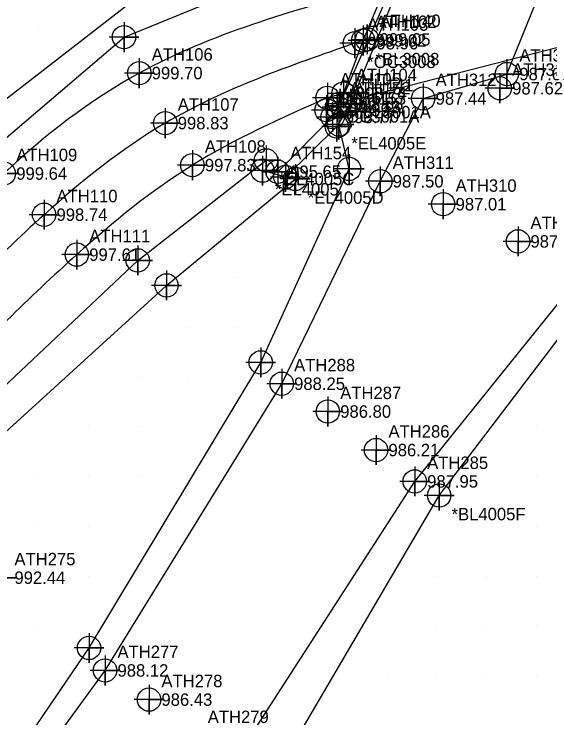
# Model space of a CAD drawing. Extents: x 1116680 to 1117499, y 661040 to 661703.
# Drawn here: x 1116955 to 1117062.7, y 661221.5 to 661363 of the extents above; entities that cross this region are included whole.
import ezdxf

# ---------------------------------------------------------------- set-up
doc = ezdxf.new("R2010")
doc.units = 0
for name, color, linetype in [('Exist DTM Breakline', 7, 'Continuous'), ('Exist DTM Breakline Cogo Comment', 7, 'Continuous'), ('Exist DTM Breakline Cogo Point CELL', 7, 'Continuous'), ('Exist DTM Crownline', 7, 'Continuous'), ('Exist DTM Crownline Cogo Comment', 7, 'Continuous'), ('Exist DTM Crownline Cogo Elevation', 7, 'Continuous'), ('Exist DTM Crownline Cogo Number', 7, 'Continuous'), ('Exist DTM Crownline Cogo Point CELL', 7, 'Continuous'), ('Exist DTM Drainline Cogo Elevation', 7, 'Continuous'), ('Exist DTM Drainline Cogo Number', 7, 'Continuous'), ('Exist DTM Drainline Cogo Point CELL', 7, 'Continuous'), ('Exist DTM QL2 LIDAR Elevation Point', 7, 'Continuous'), ('Exist DTM Regular Point CELL', 7, 'Continuous'), ('Exist DTM Regular Point Cogo Elevation', 7, 'Continuous'), ('Exist DTM Regular Point Cogo Number', 7, 'Continuous'), ('Exist DTM Regular Point Underwater CELL', 7, 'Continuous'), ('Exist DTM Regular Point Underwater Cogo Elevation', 7, 'Continuous'), ('Exist DTM Regular Point Underwater Cogo Number', 7, 'Continuous'), ('Exist Guardrail Cogo Elevation', 7, 'Continuous'), ('Exist Guardrail Cogo Point CELL', 7, 'Continuous'), ('Exist Hydro Stream or Body of Water', 7, 'Continuous'), ('Exist Roads EOP', 7, 'Continuous'), ('Exist Roads EOP Cogo Comment', 7, 'Continuous'), ('Exist Roads EOP Cogo Elevation', 7, 'Continuous'), ('Exist Roads EOP Cogo Number', 7, 'Continuous'), ('Exist Roads EOP Cogo Point CELL', 7, 'Continuous'), ('Exist Structure Major Bridge Seam Cogo Elevation', 7, 'Continuous'), ('Exist Structure Major Bridge Seam Cogo Number', 7, 'Continuous'), ('Exist Structure Major Bridge Seam Cogo Point CELL', 7, 'Continuous'), ('Exist Structure Major Bridge WW Cogo Elevation', 7, 'Continuous'), ('Exist Structure Major Bridge WW Cogo Number', 7, 'Continuous'), ('Exist Structure Major Bridge WW Cogo Point CELL', 7, 'Continuous'), ('Exist Structure Major Deck Tunnel Box Culvert', 7, 'Continuous')]:
    doc.layers.add(name, color=color, linetype=linetype)

msp = doc.modelspace()

# ---------------------------------------------------------------- linework, layer by layer
at = {"layer": 'Exist DTM Breakline'}
msp.add_line((1117005.474, 661206.472), (1117040.467, 661266.201), dxfattribs=at)
for points in [[(1116777.711, 661140.704), (1116828.227, 661198.994), (1116863.907, 661242.056), (1116901.537, 661293.371), (1116942.909, 661337.866), (1116986.207, 661371.481), (1117014.804, 661386.644), (1117027.371, 661386.959)], [(1117026.431, 661387.63), (1117029.138, 661385.793), (1117034.453, 661374.2), (1117033.842, 661372.244), (1117022.619, 661345.013), (1117019.882, 661340.396), (1117009.557, 661330.24), (1117004.953, 661331.537)], [(1116764.336, 661115.367), (1116780.79, 661135.76), (1116832.216, 661195.325), (1116868.599, 661238.611), (1116907.746, 661286.411), (1116949.649, 661334.962), (1116977.116, 661358.387), (1117017.083, 661374.758), (1117030.676, 661371.171)], [(1117019.945, 661344.369), (1117019.039, 661342.322), (1117008.012, 661331.323)], [(1117040.467, 661266.201), (1117071.81, 661307.445), (1117084.165, 661341.998)], [(1116938.631, 661189.278), (1116970.08, 661235.53), (1117004.586, 661292.975), (1117022.365, 661331.868), (1117020.311, 661340.79)], [(1116804.214, 661119.184), (1116852.32, 661176.293), (1116889.45, 661221.661), (1116930.482, 661266.919), (1116979.857, 661313.491), (1117005.659, 661333.608)], [(1116935.96, 661187.155), (1116915.624, 661198.811), (1116892.595, 661215.476), (1116935.176, 661262.478), (1116985.662, 661308.46), (1117011.556, 661329.863)]]:
    msp.add_lwpolyline(points, dxfattribs=at)
at = {"layer": 'Exist DTM Breakline Cogo Point CELL'}
for points in [[(1116977.116, 661361.387), (1116977.116, 661355.387), (1116977.116, 661358.387), (1116980.116, 661358.387), (1116974.116, 661358.387)], [(1117022.619, 661348.013), (1117022.619, 661342.013), (1117022.619, 661345.013), (1117025.619, 661345.013), (1117019.619, 661345.013)], [(1117019.882, 661343.396), (1117019.882, 661337.396), (1117019.882, 661340.396), (1117022.882, 661340.396), (1117016.882, 661340.396)], [(1117020.311, 661343.79), (1117020.311, 661337.79), (1117020.311, 661340.79), (1117023.311, 661340.79), (1117017.311, 661340.79)], [(1117005.659, 661336.608), (1117005.659, 661330.608), (1117005.659, 661333.608), (1117008.659, 661333.608), (1117002.659, 661333.608)], [(1117022.365, 661334.868), (1117022.365, 661328.868), (1117022.365, 661331.868), (1117025.365, 661331.868), (1117019.365, 661331.868)], [(1117004.953, 661334.537), (1117004.953, 661328.537), (1117004.953, 661331.537), (1117007.953, 661331.537), (1117001.953, 661331.537)], [(1117009.557, 661333.24), (1117009.557, 661327.24), (1117009.557, 661330.24), (1117012.557, 661330.24), (1117006.557, 661330.24)], [(1117011.556, 661332.863), (1117011.556, 661326.863), (1117011.556, 661329.863), (1117014.556, 661329.863), (1117008.556, 661329.863)], [(1116979.857, 661316.491), (1116979.857, 661310.491), (1116979.857, 661313.491), (1116982.857, 661313.491), (1116976.857, 661313.491)], [(1116985.662, 661311.46), (1116985.662, 661305.46), (1116985.662, 661308.46), (1116988.662, 661308.46), (1116982.662, 661308.46)], [(1117004.586, 661295.975), (1117004.586, 661289.975), (1117004.586, 661292.975), (1117007.586, 661292.975), (1117001.586, 661292.975)], [(1117040.467, 661269.201), (1117040.467, 661263.201), (1117040.467, 661266.201), (1117043.467, 661266.201), (1117037.467, 661266.201)], [(1116970.08, 661238.53), (1116970.08, 661232.53), (1116970.08, 661235.53), (1116973.08, 661235.53), (1116967.08, 661235.53)]]:
    msp.add_lwpolyline(points, dxfattribs=at)
for centre in [(1116977.116, 661358.387), (1117022.619, 661345.013), (1117020.311, 661340.79), (1117019.882, 661340.396), (1117005.659, 661333.608), (1117004.953, 661331.537), (1117022.365, 661331.868), (1117009.557, 661330.24), (1117011.556, 661329.863), (1116979.857, 661313.491), (1116985.662, 661308.46), (1117004.586, 661292.975), (1117040.467, 661266.201), (1116970.08, 661235.53)]:
    msp.add_circle(centre, 2.344, dxfattribs=at)
at = {"layer": 'Exist DTM Crownline'}
msp.add_line((1117025.187, 661357.713), (1117023.526, 661357.17), dxfattribs=at)
msp.add_spline([(1117023.526, 661357.17), (1116985.409, 661341.089), (1116961.036, 661322.674), (1116932.907, 661294.206), (1116917.938, 661277.457)], degree=3, dxfattribs=at)
at = {"layer": 'Exist DTM Crownline Cogo Point CELL'}
for points in [[(1117023.526, 661360.17), (1117023.526, 661354.17), (1117023.526, 661357.17), (1117026.526, 661357.17), (1117020.526, 661357.17)], [(1117025.187, 661360.713), (1117025.187, 661354.713), (1117025.187, 661357.713), (1117028.187, 661357.713), (1117022.187, 661357.713)], [(1116985.409, 661344.089), (1116985.409, 661338.089), (1116985.409, 661341.089), (1116988.409, 661341.089), (1116982.409, 661341.089)], [(1116961.036, 661325.674), (1116961.036, 661319.674), (1116961.036, 661322.674), (1116964.036, 661322.674), (1116958.036, 661322.674)]]:
    msp.add_lwpolyline(points, dxfattribs=at)
for centre in [(1117025.187, 661357.713), (1117023.526, 661357.17), (1116985.409, 661341.089), (1116961.036, 661322.674)]:
    msp.add_circle(centre, 2.344, dxfattribs=at)
at = {"layer": 'Exist DTM Drainline Cogo Point CELL'}
for points in [[(1117054.084, 661353.959), (1117054.084, 661347.959), (1117054.084, 661350.959), (1117057.084, 661350.959), (1117051.084, 661350.959)], [(1117037.259, 661349.044), (1117037.259, 661343.044), (1117037.259, 661346.044), (1117040.259, 661346.044), (1117034.259, 661346.044)], [(1117028.625, 661332.39), (1117028.625, 661326.39), (1117028.625, 661329.39), (1117031.625, 661329.39), (1117025.625, 661329.39)], [(1117008.806, 661291.675), (1117008.806, 661285.675), (1117008.806, 661288.675), (1117011.806, 661288.675), (1117005.806, 661288.675)], [(1117035.553, 661272.03), (1117035.553, 661266.03), (1117035.553, 661269.03), (1117038.553, 661269.03), (1117032.553, 661269.03)], [(1116973.299, 661234.015), (1116973.299, 661228.015), (1116973.299, 661231.015), (1116976.299, 661231.015), (1116970.299, 661231.015)]]:
    msp.add_lwpolyline(points, dxfattribs=at)
for centre in [(1117054.084, 661350.959), (1117037.259, 661346.044), (1117028.625, 661329.39), (1117008.806, 661288.675), (1117035.553, 661269.03), (1116973.299, 661231.015)]:
    msp.add_circle(centre, 2.344, dxfattribs=at)
at = {"layer": 'Exist DTM QL2 LIDAR Elevation Point'}
for p, q in [((1116960, 661360), (1116960, 661360)), ((1117000, 661310), (1117000, 661310)), ((1116990, 661300), (1116990, 661300)), ((1117000, 661300), (1117000, 661300)), ((1116980, 661290), (1116980, 661290)), ((1116990, 661290), (1116990, 661290)), ((1116970, 661280), (1116970, 661280)), ((1116980, 661280), (1116980, 661280)), ((1117060, 661280), (1117060, 661280)), ((1116960, 661270), (1116960, 661270)), ((1116970, 661270), (1116970, 661270)), ((1116980, 661270), (1116980, 661270)), ((1117060, 661270), (1117060, 661270)), ((1116960, 661260), (1116960, 661260)), ((1116970, 661260), (1116970, 661260)), ((1117050, 661260), (1117050, 661260)), ((1117060, 661260), (1117060, 661260)), ((1116960, 661250), (1116960, 661250)), ((1116970, 661250), (1116970, 661250)), ((1117040, 661250), (1117040, 661250)), ((1117050, 661250), (1117050, 661250)), ((1117060, 661250), (1117060, 661250)), ((1116960, 661240), (1116960, 661240)), ((1117040, 661240), (1117040, 661240)), ((1117050, 661240), (1117050, 661240)), ((1117060, 661240), (1117060, 661240)), ((1117030, 661230), (1117030, 661230)), ((1117040, 661230), (1117040, 661230)), ((1117050, 661230), (1117050, 661230)), ((1117060, 661230), (1117060, 661230))]:
    msp.add_line(p, q, dxfattribs=at)
at = {"layer": 'Exist DTM Regular Point CELL'}
msp.add_lwpolyline([(1116952.58, 661252.659), (1116952.58, 661246.659), (1116952.58, 661249.659), (1116955.58, 661249.659), (1116949.58, 661249.659)], dxfattribs=at)
at = {"layer": 'Exist DTM Regular Point Underwater CELL'}
for points in [[(1117052.644, 661351.104), (1117052.644, 661345.104), (1117052.644, 661348.104), (1117055.644, 661348.104), (1117049.644, 661348.104)], [(1117041.273, 661327.781), (1117041.273, 661321.781), (1117041.273, 661324.781), (1117044.273, 661324.781), (1117038.273, 661324.781)], [(1117056.32, 661320.301), (1117056.32, 661314.301), (1117056.32, 661317.301), (1117059.32, 661317.301), (1117053.32, 661317.301)], [(1117018.077, 661286.085), (1117018.077, 661280.085), (1117018.077, 661283.085), (1117021.077, 661283.085), (1117015.077, 661283.085)], [(1117027.778, 661278.34), (1117027.778, 661272.34), (1117027.778, 661275.34), (1117030.778, 661275.34), (1117024.778, 661275.34)], [(1116982.133, 661228.142), (1116982.133, 661222.142), (1116982.133, 661225.142), (1116985.133, 661225.142), (1116979.133, 661225.142)]]:
    msp.add_lwpolyline(points, dxfattribs=at)
for centre in [(1117052.644, 661348.104), (1117041.273, 661324.781), (1117056.32, 661317.301), (1117018.077, 661283.085), (1117027.778, 661275.34), (1116982.133, 661225.142)]:
    msp.add_circle(centre, 2.344, dxfattribs=at)
at = {"layer": 'Exist Guardrail Cogo Point CELL'}
msp.add_lwpolyline([(1117017.81, 661346.693), (1117017.81, 661340.693), (1117017.81, 661343.693), (1117020.81, 661343.693), (1117014.81, 661343.693)], dxfattribs=at)
msp.add_circle((1117017.81, 661343.693), 2.344, dxfattribs=at)
at = {"layer": 'Exist Hydro Stream or Body of Water'}
for points in [[(1116885.259, 661065.084), (1116909.522, 661128.826), (1116941.429, 661187.261), (1116973.299, 661231.015), (1117008.806, 661288.675), (1117028.625, 661329.39), (1117037.259, 661346.044), (1117054.084, 661350.959), (1117065.864, 661380.085), (1117058.435, 661381.413), (1117066.561, 661417.266), (1117077.352, 661449.252), (1117098.924, 661488.98)], [(1116999.252, 661212.663), (1117035.553, 661269.03), (1117067.842, 661309.057), (1117080.473, 661351.773), (1117079.751, 661359.687), (1117095.986, 661391.983), (1117110.725, 661432.453), (1117125.362, 661468.034)]]:
    msp.add_lwpolyline(points, dxfattribs=at)
at = {"layer": 'Exist Roads EOP'}
msp.add_line((1117021.234, 661347.049), (1117018.008, 661346.187), dxfattribs=at)
msp.add_lwpolyline([(1117021.234, 661347.049), (1117025.187, 661357.713), (1117029.838, 661368.807)], dxfattribs=at)
for points in [[(1117026.904, 661368.114), (1116980.178, 661351.152), (1116952.946, 661330.95), (1116925.984, 661301.817)], [(1117018.008, 661346.187), (1116990.857, 661332.639), (1116967.617, 661314.642), (1116940.103, 661287.744), (1116924.898, 661271.684)]]:
    msp.add_spline(points, degree=3, dxfattribs=at)
at = {"layer": 'Exist Roads EOP Cogo Point CELL'}
for points in [[(1116980.178, 661354.152), (1116980.178, 661348.152), (1116980.178, 661351.152), (1116983.178, 661351.152), (1116977.178, 661351.152)], [(1117018.008, 661349.187), (1117018.008, 661343.187), (1117018.008, 661346.187), (1117021.008, 661346.187), (1117015.008, 661346.187)], [(1117021.234, 661350.049), (1117021.234, 661344.049), (1117021.234, 661347.049), (1117024.234, 661347.049), (1117018.234, 661347.049)], [(1116990.857, 661335.639), (1116990.857, 661329.639), (1116990.857, 661332.639), (1116993.857, 661332.639), (1116987.857, 661332.639)], [(1116952.946, 661333.95), (1116952.946, 661327.95), (1116952.946, 661330.95), (1116955.946, 661330.95), (1116949.946, 661330.95)], [(1116967.617, 661317.642), (1116967.617, 661311.642), (1116967.617, 661314.642), (1116970.617, 661314.642), (1116964.617, 661314.642)]]:
    msp.add_lwpolyline(points, dxfattribs=at)
for centre in [(1116980.178, 661351.152), (1117021.234, 661347.049), (1117018.008, 661346.187), (1116990.857, 661332.639), (1116952.946, 661330.95), (1116967.617, 661314.642)]:
    msp.add_circle(centre, 2.344, dxfattribs=at)
at = {"layer": 'Exist Structure Major Bridge Seam Cogo Point CELL'}
for points in [[(1117022.993, 661357.928), (1117028.993, 661357.928), (1117025.993, 661357.928), (1117025.993, 661360.928), (1117025.993, 661354.928)], [(1117017.55, 661345.005), (1117023.55, 661345.005), (1117020.55, 661345.005), (1117020.55, 661348.005), (1117020.55, 661342.005)]]:
    msp.add_lwpolyline(points, dxfattribs=at)
for centre in [(1117025.993, 661357.928), (1117020.55, 661345.005)]:
    msp.add_circle(centre, 2.344, dxfattribs=at)
at = {"layer": 'Exist Structure Major Bridge WW Cogo Point CELL'}
for points in [[(1117016.945, 661344.369), (1117022.945, 661344.369), (1117019.945, 661344.369), (1117019.945, 661347.369), (1117019.945, 661341.369)], [(1117016.039, 661342.322), (1117022.039, 661342.322), (1117019.039, 661342.322), (1117019.039, 661345.322), (1117019.039, 661339.322)], [(1117005.012, 661331.323), (1117011.012, 661331.323), (1117008.012, 661331.323), (1117008.012, 661334.323), (1117008.012, 661328.323)]]:
    msp.add_lwpolyline(points, dxfattribs=at)
for centre in [(1117019.945, 661344.369), (1117019.039, 661342.322), (1117008.012, 661331.323)]:
    msp.add_circle(centre, 2.344, dxfattribs=at)
at = {"layer": 'Exist Structure Major Deck Tunnel Box Culvert'}
msp.add_lwpolyline([(1117031.737, 661370.434), (1117096.438, 661387.065), (1117083.188, 661361.127), (1117020.55, 661345.005), (1117031.737, 661370.434)], dxfattribs=at)

# ---------------------------------------------------------------- texts
at = {"layer": 'Exist DTM Breakline Cogo Comment'}
for s, p in [('*EL4005E', (1117022.811, 661335.79)), ('*EL4005C', (1117008.159, 661328.608)), ('*EL4005', (1117007.453, 661326.537)), ('*EL4005D', (1117014.056, 661324.863)), ('*BL4005F', (1117042.967, 661261.201))]:
    msp.add_text(s, height=2.5, dxfattribs=at).set_placement(p)
at = {"layer": 'Exist DTM Crownline Cogo Comment'}
for s, p in [('*OC3008', (1117026.026, 661352.17)), ('*BL3008', (1117027.687, 661352.713))]:
    msp.add_text(s, height=2.5, dxfattribs=at).set_placement(p)
at = {"layer": 'Exist DTM Crownline Cogo Elevation'}
for s, p in [('999.02', (1117027.687, 661356.463)), ('998.96', (1117026.026, 661355.92)), ('998.83', (1116987.909, 661339.839)), ('998.74', (1116963.536, 661321.424))]:
    msp.add_text(s, height=2.5, dxfattribs=at).set_placement(p)
at = {"layer": 'Exist DTM Crownline Cogo Number'}
for s, p in [('ATH103', (1117026.026, 661359.67)), ('ATH102', (1117027.687, 661360.213)), ('ATH107', (1116987.909, 661343.589)), ('ATH110', (1116963.536, 661325.174))]:
    msp.add_text(s, height=2.5, dxfattribs=at).set_placement(p)
at = {"layer": 'Exist DTM Drainline Cogo Elevation'}
for s, p in [('987.60', (1117056.584, 661349.709)), ('987.44', (1117039.759, 661344.794)), ('987.50', (1117031.125, 661328.14)), ('988.25', (1117011.306, 661287.425)), ('987.95', (1117038.053, 661267.78)), ('988.12', (1116975.799, 661229.765))]:
    msp.add_text(s, height=2.5, dxfattribs=at).set_placement(p)
at = {"layer": 'Exist DTM Drainline Cogo Number'}
for s, p in [('ATH317', (1117056.584, 661353.459)), ('ATH312', (1117039.759, 661348.544)), ('ATH311', (1117031.125, 661331.89)), ('ATH288', (1117011.306, 661291.175)), ('ATH285', (1117038.053, 661271.53)), ('ATH277', (1116975.799, 661233.515))]:
    msp.add_text(s, height=2.5, dxfattribs=at).set_placement(p)
at = {"layer": 'Exist DTM Regular Point Cogo Elevation'}
msp.add_text('992.44', height=2.5, dxfattribs=at).set_placement((1116955.08, 661248.409))
at = {"layer": 'Exist DTM Regular Point Cogo Number'}
msp.add_text('ATH275', height=2.5, dxfattribs=at).set_placement((1116955.08, 661252.159))
at = {"layer": 'Exist DTM Regular Point Underwater Cogo Elevation'}
for s, p in [('987.62', (1117055.144, 661346.854)), ('987.01', (1117043.773, 661323.531)), ('987.27', (1117058.82, 661316.051)), ('986.80', (1117020.577, 661281.835)), ('986.21', (1117030.278, 661274.09)), ('986.43', (1116984.633, 661223.892))]:
    msp.add_text(s, height=2.5, dxfattribs=at).set_placement(p)
at = {"layer": 'Exist DTM Regular Point Underwater Cogo Number'}
for s, p in [('ATH313', (1117055.144, 661350.604)), ('ATH310', (1117043.773, 661327.281)), ('ATH309', (1117058.82, 661319.801)), ('ATH287', (1117020.577, 661285.585)), ('ATH286', (1117030.278, 661277.84)), ('ATH278', (1116984.633, 661227.642)), ('ATH279', (1116993.941, 661220.431))]:
    msp.add_text(s, height=2.5, dxfattribs=at).set_placement(p)
at = {"layer": 'Exist Guardrail Cogo Elevation'}
msp.add_text('997.99', height=2.5, dxfattribs=at).set_placement((1117020.31, 661342.443))
at = {"layer": 'Exist Roads EOP Cogo Comment'}
for s, p in [('*BL3001A', (1117023.734, 661342.049)), ('*OC3001A', (1117020.508, 661341.187))]:
    msp.add_text(s, height=2.5, dxfattribs=at).set_placement(p)
at = {"layer": 'Exist Roads EOP Cogo Elevation'}
for s, p in [('999.70', (1116982.678, 661349.902)), ('998.61', (1117020.508, 661344.937)), ('998.74', (1117023.734, 661345.799)), ('997.83', (1116993.357, 661331.389)), ('999.64', (1116955.446, 661329.7)), ('997.61', (1116970.117, 661313.392))]:
    msp.add_text(s, height=2.5, dxfattribs=at).set_placement(p)
at = {"layer": 'Exist Roads EOP Cogo Number'}
for s, p in [('ATH106', (1116982.678, 661353.652)), ('ATH104', (1117023.734, 661349.549)), ('ATH105', (1117020.508, 661348.687)), ('ATH108', (1116993.357, 661335.139)), ('ATH109', (1116955.446, 661333.45)), ('ATH111', (1116970.117, 661317.142))]:
    msp.add_text(s, height=2.5, dxfattribs=at).set_placement(p)
at = {"layer": 'Exist Structure Major Bridge Seam Cogo Elevation'}
for s, p in [('999.05', (1117028.493, 661356.678)), ('998.88', (1117023.05, 661343.755))]:
    msp.add_text(s, height=2.5, dxfattribs=at).set_placement(p)
at = {"layer": 'Exist Structure Major Bridge Seam Cogo Number'}
for s, p in [('ATH140', (1117028.493, 661360.428)), ('ATH141', (1117023.05, 661347.505))]:
    msp.add_text(s, height=2.5, dxfattribs=at).set_placement(p)
at = {"layer": 'Exist Structure Major Bridge WW Cogo Elevation'}
for s, p in [('998.73', (1117022.445, 661343.119)), ('998.77', (1117021.539, 661341.072)), ('995.65', (1117010.512, 661330.073))]:
    msp.add_text(s, height=2.5, dxfattribs=at).set_placement(p)
at = {"layer": 'Exist Structure Major Bridge WW Cogo Number'}
for s, p in [('ATH152', (1117022.445, 661346.869)), ('ATH153', (1117021.539, 661344.822)), ('ATH154', (1117010.512, 661333.823))]:
    msp.add_text(s, height=2.5, dxfattribs=at).set_placement(p)

doc.saveas('drawing.dxf')
